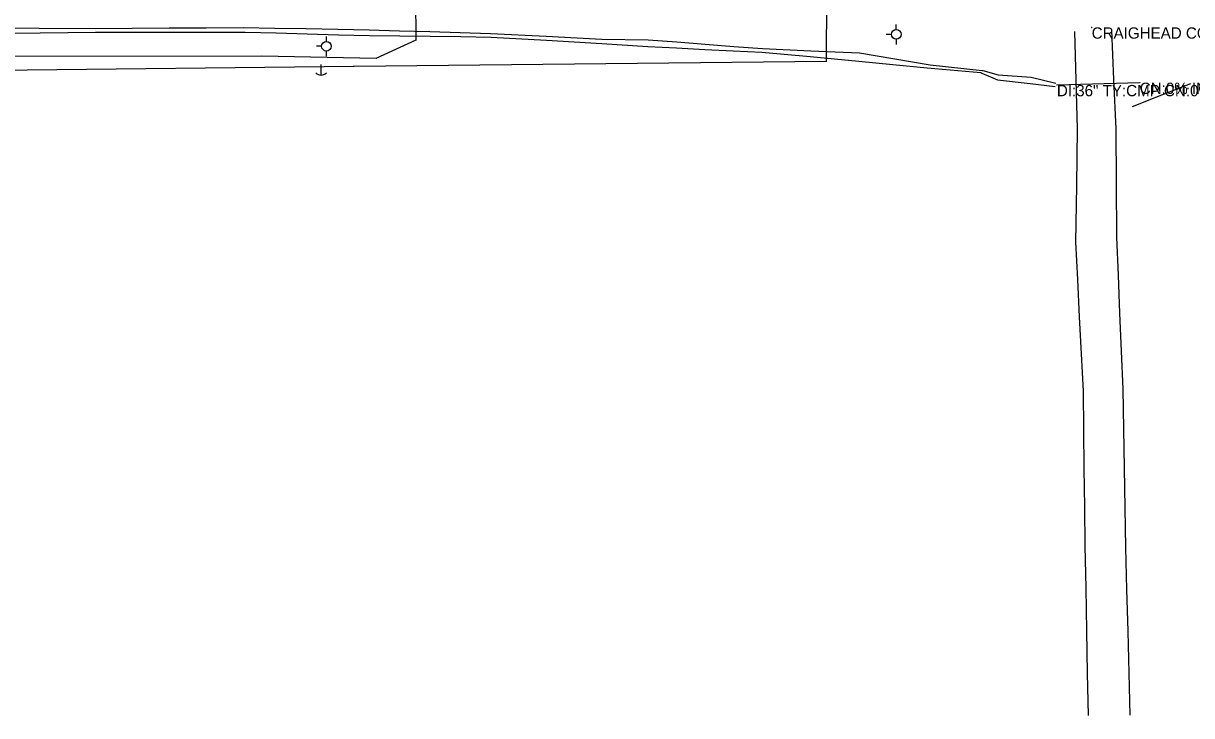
# Model space of a CAD drawing. Extents: x 1800653 to 1804042, y 522635 to 523313.
# Drawn here: x 1801731 to 1802247, y 522637 to 522943 of the extents above; entities that cross this region are included whole.
import ezdxf

# ---------------------------------------------------------------- set-up
doc = ezdxf.new("R2010")
doc.units = 0
for name, color, linetype in [('S_DITCHLINE', 7, 'Continuous'), ('S_DRG_PT_SYM', 7, 'Continuous'), ('S_GAS_UTILITIES', 7, 'Continuous'), ('S_GRAVEL_ROAD', 7, 'Continuous'), ('S_MSC_PT_SYM', 7, 'Continuous'), ('S_SIDE_DRAIN', 7, 'Continuous'), ('S_SIDE_DRAIN_ANNOT', 7, 'Continuous'), ('S_SURVEY_TEXT_ANNOT', 7, 'Continuous'), ('S_UTILITY_POLE', 7, 'Continuous'), ('S_UTL_PT_SYM', 7, 'Continuous'), ('S_WATER_UTILITIES', 7, 'Continuous')]:
    doc.layers.add(name, color=color, linetype=linetype)

msp = doc.modelspace()

# ---------------------------------------------------------------- linework, layer by layer
at = {"layer": 'S_DITCHLINE'}
for points in [[(1801713.26, 522940.8), (1801737.87, 522940.67), (1801762.48, 522940.55), (1801778.84, 522940.66), (1801795.2, 522940.77), (1801811.55, 522940.88), (1801827.91, 522940.99), (1801841.84, 522940.73), (1801855.77, 522940.47), (1801869.7, 522940.22), (1801883.62, 522939.96), (1801897, 522939.56), (1801910.38, 522939.15), (1801923.76, 522938.75), (1801937.13, 522938.35), (1801961.76, 522937.08), (1801986.39, 522935.8), (1802006.82, 522935.53), (1802019.44, 522934.56), (1802032.05, 522933.59), (1802044.67, 522932.61), (1802057.29, 522931.64), (1802078.72, 522930.71), (1802100.15, 522929.77), (1802115.76, 522927.09), (1802131.36, 522924.41), (1802154.3, 522921.94), (1802154.6, 522921.9), (1802161.39, 522920.01), (1802176.03, 522919.01), (1802186.93, 522916.42)], [(1801713.63, 522938.32), (1801738.18, 522938.62), (1801762.74, 522938.92), (1801779.24, 522938.92), (1801795.75, 522938.92), (1801812.26, 522938.92), (1801828.76, 522938.92), (1801842.5, 522938.55), (1801856.23, 522938.17), (1801869.96, 522937.79), (1801883.69, 522937.41), (1801897.13, 522937.25), (1801910.57, 522937.09), (1801924.01, 522936.92), (1801937.44, 522936.76), (1801961.89, 522935.3), (1801986.34, 522933.84), (1802006.7, 522932.56), (1802019.26, 522931.93), (1802031.82, 522931.3), (1802044.38, 522930.67), (1802056.94, 522930.04), (1802078.37, 522928.08), (1802099.8, 522926.12), (1802114.94, 522924.61), (1802130.08, 522923.1), (1802153.78, 522921.06), (1802154.24, 522920.82), (1802161.05, 522917.87), (1802175.52, 522916.18), (1802186.52, 522914.84)], [(1802246.37, 522916.12), (1802233.47, 522911.01), (1802220.57, 522905.9)]]:
    msp.add_lwpolyline(points, dxfattribs=at)
at = {"layer": 'S_DRG_PT_SYM'}
for points in [[(1802187.32, 522915.58), (1802187.32, 522915.63), (1802187.32, 522915.58), (1802187.27, 522915.58), (1802187.32, 522915.58), (1802187.32, 522915.53), (1802187.32, 522915.58), (1802187.37, 522915.58)], [(1802223.95, 522916.59), (1802223.95, 522916.64), (1802223.95, 522916.59), (1802223.9, 522916.59), (1802223.95, 522916.59), (1802223.95, 522916.54), (1802223.95, 522916.59), (1802224, 522916.59)]]:
    msp.add_lwpolyline(points, dxfattribs=at)
at = {"layer": 'S_GAS_UTILITIES'}
for p, q in [((1801904.38, 522935.52), (1801904.05, 522964.06)), ((1801886.73, 522927.35), (1801904.38, 522935.52)), ((1801313.07, 522927.87), (1801836.17, 522928.43)), ((1801836.17, 522928.43), (1801886.73, 522927.35))]:
    msp.add_line(p, q, dxfattribs=at)
at = {"layer": 'S_GRAVEL_ROAD'}
for points in [[(1802195.13, 522939.21), (1802195.74, 522917.67), (1802196.35, 522896.13), (1802195.94, 522871.15), (1802195.53, 522846.17), (1802196.37, 522829.69), (1802197.22, 522813.21), (1802198.06, 522796.72), (1802198.91, 522780.24), (1802199.1, 522763.18), (1802199.3, 522746.12), (1802199.5, 522729.05), (1802199.7, 522711.99), (1802200.06, 522693.23), (1802200.42, 522674.47), (1802200.78, 522655.71), (1802201.13, 522636.95)], [(1802211.42, 522939.8), (1802212.37, 522918.01), (1802213.31, 522896.22), (1802213.46, 522872.24), (1802213.61, 522848.26), (1802214.33, 522831.49), (1802215.05, 522814.73), (1802215.77, 522797.96), (1802216.49, 522781.19), (1802216.79, 522763.7), (1802217.08, 522746.21), (1802217.38, 522728.72), (1802217.68, 522711.23), (1802218.15, 522692.73), (1802218.62, 522674.22), (1802219.09, 522655.72), (1802219.55, 522637.22)]]:
    msp.add_lwpolyline(points, dxfattribs=at)
at = {"layer": 'S_MSC_PT_SYM'}
msp.add_lwpolyline([(1802202.71, 522941.02), (1802202.71, 522941.07), (1802202.71, 522941.02), (1802202.66, 522941.02), (1802202.71, 522941.02), (1802202.71, 522940.97), (1802202.71, 522941.02), (1802202.76, 522941.02)], dxfattribs=at)
at = {"layer": 'S_SIDE_DRAIN'}
msp.add_line((1802187.32, 522915.58), (1802223.95, 522916.59), dxfattribs=at)
at = {"layer": 'S_UTILITY_POLE'}
for p, q in [((1802116.38, 522940.02), (1802116.38, 522942.26)), ((1801864.68, 522934.79), (1801864.68, 522937.03)), ((1802114.29, 522937.88), (1802111.96, 522937.88)), ((1802116.46, 522933.47), (1802116.46, 522935.79)), ((1801862.59, 522932.66), (1801860.27, 522932.66)), ((1801864.76, 522928.24), (1801864.76, 522930.56)), ((1801862.25, 522924.63), (1801862.25, 522919.9))]:
    msp.add_line(p, q, dxfattribs=at)
for centre in [(1802116.38, 522937.91), (1801864.69, 522932.68)]:
    msp.add_circle(centre, 2.13, dxfattribs=at)
msp.add_arc((1801862.32, 522923.33), 3.41, 226.3972, 313.6028, dxfattribs=at)
at = {"layer": 'S_UTL_PT_SYM'}
for points in [[(1801904.38, 522935.52), (1801904.38, 522935.57), (1801904.38, 522935.52), (1801904.33, 522935.52), (1801904.38, 522935.52), (1801904.38, 522935.47), (1801904.38, 522935.52), (1801904.43, 522935.52)], [(1801836.17, 522928.43), (1801836.17, 522928.48), (1801836.17, 522928.43), (1801836.12, 522928.43), (1801836.17, 522928.43), (1801836.17, 522928.38), (1801836.17, 522928.43), (1801836.22, 522928.43)], [(1801876.84, 522923.94), (1801876.84, 522923.99), (1801876.84, 522923.94), (1801876.79, 522923.94), (1801876.84, 522923.94), (1801876.84, 522923.89), (1801876.84, 522923.94), (1801876.89, 522923.94)], [(1801886.73, 522927.35), (1801886.73, 522927.4), (1801886.73, 522927.35), (1801886.68, 522927.35), (1801886.73, 522927.35), (1801886.73, 522927.3), (1801886.73, 522927.35), (1801886.78, 522927.35)], [(1802085.62, 522926.08), (1802085.62, 522926.13), (1802085.62, 522926.08), (1802085.57, 522926.08), (1802085.62, 522926.08), (1802085.62, 522926.03), (1802085.62, 522926.08), (1802085.67, 522926.08)]]:
    msp.add_lwpolyline(points, dxfattribs=at)
at = {"layer": 'S_WATER_UTILITIES'}
for p, q in [((1802085.62, 522926.08), (1802085.7, 522965.18)), ((1801625.6, 522920.92), (1801876.84, 522923.94)), ((1801876.84, 522923.94), (1802085.62, 522926.08))]:
    msp.add_line(p, q, dxfattribs=at)

# ---------------------------------------------------------------- texts
at = {"layer": 'S_SIDE_DRAIN_ANNOT'}
for s, p in [('DI:36" TY:CMP CN:0% LN:37\' INVE', (1802187.32, 522910.58)), ('CN:0% INVERT OF PIPE', (1802223.95, 522911.59))]:
    msp.add_text(s, height=5, dxfattribs=at).set_placement(p)
at = {"layer": 'S_SURVEY_TEXT_ANNOT'}
msp.add_text('CRAIGHEAD CO RD 864', height=5, dxfattribs=at).set_placement((1802202.71, 522936.02))

doc.saveas('drawing.dxf')
